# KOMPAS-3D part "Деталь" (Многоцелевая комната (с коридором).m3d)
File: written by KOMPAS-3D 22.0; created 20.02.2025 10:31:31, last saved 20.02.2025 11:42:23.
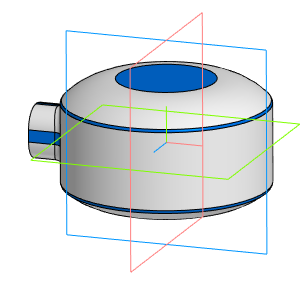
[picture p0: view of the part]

Document properties: Автор: Пользователь Windows; Полное имя файла: C:\Users\Student\Documents\Картошечка\База Сабнатика\Многоцелевая комната\Многоцелевая комната (с коридором).m3d

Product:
- Part/product: Деталь
    Масса: 0.428066

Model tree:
1. Эскиз:3
2. Элемент вращения:1
     Угол 1 = 360
3. Скругление:1  (with: Элемент вращения:1)
     Радиус = 1
4. Эскиз:4
5. Элемент выдавливания:1
     Расстояние 1 = 32.5
6. Скругление:3  (with: Элемент выдавливания:1)
     Радиус = 2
